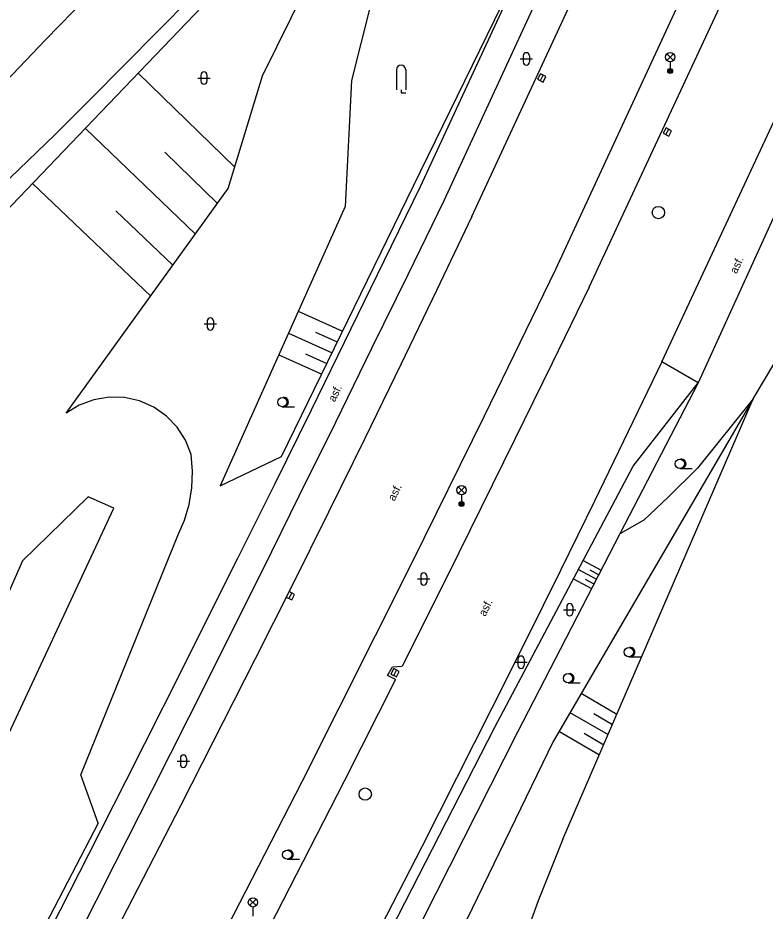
# Model space of a CAD drawing. Extents: x -596024 to -594475, y -1163820 to -1161957.
# Drawn here: x -595661.6 to -595600.9, y -1162932.2 to -1162859.7 of the extents above; entities that cross this region are included whole.
import ezdxf

# ---------------------------------------------------------------- set-up
doc = ezdxf.new("R2010")
doc.units = 0
for name, color, linetype in [('Level 10', 7, 'Continuous'), ('Level 11', 7, 'Continuous'), ('Level 14', 7, 'Continuous'), ('Level 15', 7, 'Continuous'), ('Level 27', 7, 'Continuous'), ('Level 33', 7, 'Continuous'), ('Level 36', 7, 'Continuous'), ('Level 40', 7, 'Continuous')]:
    doc.layers.add(name, color=color, linetype=linetype)

msp = doc.modelspace()

# ---------------------------------------------------------------- linework, layer by layer
at = {"layer": 'Level 10'}
for points in [[(-595666.85, -1162869.3), (-595659.35, -1162861.44), (-595655.97, -1162857.97), (-595636.92, -1162838.39)], [(-595609.25, -1162887.61), (-595595.09, -1162857.2), (-595590.93, -1162847.22)], [(-595642.02, -1162852.43), (-595655.68, -1162866.28)], [(-595624.69, -1162875.81), (-595613.55, -1162851.79)], [(-595617.87, -1162880.07), (-595606.7, -1162855.95)], [(-595615.16, -1162881.55), (-595603.8, -1162857.18)], [(-595655.68, -1162866.28), (-595658.6, -1162869.16)], [(-595658.6, -1162869.16), (-595667.34, -1162877.57)], [(-595624.69, -1162875.81), (-595627.57, -1162881.82), (-595630.47, -1162887.83), (-595633.4, -1162893.82), (-595636.34, -1162899.8), (-595639.31, -1162905.77), (-595642.3, -1162911.73), (-595648.35, -1162923.62), (-595651.4, -1162929.55), (-595654.48, -1162935.46)], [(-595647.58, -1162939.39), (-595641.51, -1162927.59), (-595638.5, -1162921.68), (-595632.53, -1162909.83), (-595629.56, -1162903.89), (-595623.68, -1162892), (-595620.77, -1162886.04), (-595617.87, -1162880.07)], [(-595615.16, -1162881.55), (-595618.17, -1162887.72), (-595621.19, -1162893.88), (-595625.75, -1162903.11), (-595628.82, -1162909.25), (-595630.36, -1162912.32)], [(-595609.25, -1162887.61), (-595611.98, -1162893.26), (-595614.73, -1162898.91), (-595617.49, -1162904.55), (-595620.28, -1162910.17), (-595623.09, -1162915.79), (-595628.77, -1162926.99), (-595631.63, -1162932.57), (-595634.52, -1162938.15), (-595637.43, -1162943.71), (-595640.83, -1162950.2), (-595641.83, -1162952.08)], [(-595630.9, -1162913.4), (-595631.56, -1162913.09), (-595631.14, -1162912.37), (-595630.36, -1162912.32)], [(-595630.9, -1162913.4), (-595635.07, -1162921.66), (-595637.88, -1162927.16), (-595644.94, -1162940.88), (-595648.1, -1162946.98), (-595654.57, -1162959.11), (-595657.88, -1162965.13), (-595661.23, -1162971.12), (-595664.64, -1162977.09), (-595671.6, -1162988.94), (-595675.15, -1162994.82), (-595678.75, -1163000.67)]]:
    msp.add_lwpolyline(points, dxfattribs=at)
at = {"layer": 'Level 11'}
for points in [[(-595628.87, -1162873.35), (-595618.01, -1162849.92)], [(-595615.97, -1162850.7), (-595626.98, -1162874.52)], [(-595592.14, -1162858.24), (-595606.31, -1162889.3)], [(-595658.89, -1162933.6), (-595655.83, -1162927.6), (-595652.78, -1162921.6), (-595649.75, -1162915.59), (-595643.72, -1162903.56), (-595640.72, -1162897.53), (-595637.74, -1162891.49), (-595631.81, -1162879.4), (-595628.87, -1162873.35)], [(-595626.98, -1162874.52), (-595629.91, -1162880.53), (-595632.84, -1162886.53), (-595635.79, -1162892.53), (-595638.75, -1162898.52), (-595641.72, -1162904.51), (-595647.7, -1162916.46), (-595650.71, -1162922.43), (-595653.73, -1162928.39), (-595656.76, -1162934.35)], [(-595606.31, -1162889.3), (-595609.25, -1162887.61)]]:
    msp.add_lwpolyline(points, dxfattribs=at)
at = {"layer": 'Level 14'}
for points in [[(-595641.72, -1162864.38), (-595632.4, -1162845.51)], [(-595629.74, -1162845.95), (-595634.48, -1162864.75)], [(-595628.88, -1162872.15), (-595618.01, -1162849.92)], [(-595640.93, -1162852.78), (-595654.84, -1162867.33)], [(-595644.49, -1162873.53), (-595641.72, -1162864.38)], [(-595634.48, -1162864.75), (-595634.98, -1162874.99)], [(-595654.84, -1162867.33), (-595665.74, -1162878.67)], [(-595601.84, -1162890.6), (-595588.98, -1162869.09)], [(-595640.16, -1162895.29), (-595628.88, -1162872.15)], [(-595657.67, -1162891.78), (-595644.49, -1162873.53)], [(-595634.98, -1162874.99), (-595645.16, -1162897.67)], [(-595606.31, -1162889.3), (-595612.66, -1162901.56)], [(-595611.58, -1162896.08), (-595606.31, -1162889.3)], [(-595648.58, -1162901.72), (-595648.05, -1162900.47), (-595647.68, -1162899.18), (-595647.46, -1162897.84), (-595647.4, -1162896.49), (-595647.5, -1162895.14), (-595647.97, -1162893.97), (-595648.65, -1162892.92), (-595649.52, -1162892.01), (-595650.55, -1162891.29), (-595651.7, -1162890.78), (-595652.93, -1162890.51), (-595654.18, -1162890.47), (-595655.42, -1162890.68), (-595656.6, -1162891.12), (-595657.67, -1162891.78)], [(-595601.84, -1162890.6), (-595618.1, -1162918.43)], [(-595617.29, -1162926.37), (-595601.84, -1162890.6)], [(-595601.84, -1162890.6), (-595606.36, -1162896.25)], [(-595645.16, -1162897.67), (-595640.16, -1162895.29)], [(-595622.83, -1162917.27), (-595611.58, -1162896.08)], [(-595606.36, -1162896.25), (-595608.75, -1162898.59)], [(-595653.8, -1162899.5), (-595655.89, -1162898.57), (-595661.22, -1162903.76), (-595672.02, -1162928.27), (-595680.8, -1162945.81), (-595691.23, -1162965.13), (-595695.5, -1162972.6), (-595709.49, -1162982.92)], [(-595608.75, -1162898.59), (-595610.72, -1162900.46)], [(-595694, -1162973.34), (-595689.15, -1162966.33), (-595677.69, -1162948.07), (-595668.07, -1162930.04), (-595656.91, -1162906.16), (-595653.8, -1162899.5)], [(-595610.72, -1162900.46), (-595612.66, -1162901.56)], [(-595656.47, -1162921.15), (-595648.58, -1162901.72)], [(-595612.66, -1162901.56), (-595621, -1162917.67)], [(-595636.88, -1162944.7), (-595622.83, -1162917.27)], [(-595621, -1162917.67), (-595635.37, -1162946.08)], [(-595618.1, -1162918.43), (-595632.55, -1162948.24)], [(-595655.07, -1162925.07), (-595656.47, -1162921.15)], [(-595655.07, -1162925.07), (-595659.36, -1162933.31)], [(-595617.29, -1162926.37), (-595619.32, -1162931.37), (-595620.7, -1162935.17), (-595621.54, -1162937.73), (-595622.29, -1162940.15), (-595623.72, -1162944.65), (-595624.86, -1162948), (-595626.2, -1162951.77), (-595627.28, -1162954.87), (-595628.34, -1162957.98), (-595629.37, -1162961.09), (-595630.38, -1162964.22), (-595631.21, -1162966.82), (-595631.94, -1162968.89), (-595632.76, -1162970.93), (-595634.11, -1162973.93), (-595635.11, -1162975.89), (-595636.24, -1162977.96), (-595638.63, -1162982.01), (-595639.88, -1162984.01), (-595641.18, -1162985.97)]]:
    msp.add_lwpolyline(points, dxfattribs=at)
at = {"layer": 'Level 15'}
for points in [[(-595651.82, -1162864.17), (-595643.97, -1162871.8)], [(-595656.11, -1162868.65), (-595647.17, -1162877.24)], [(-595649.66, -1162870.57), (-595645.36, -1162874.73)], [(-595660.41, -1162873.12), (-595650.8, -1162882.27)], [(-595653.63, -1162875.33), (-595648.99, -1162879.76)], [(-595638.8, -1162883.5), (-595635.2, -1162885.12)], [(-595639.59, -1162885.27), (-595636.05, -1162886.86)], [(-595637.41, -1162885.19), (-595635.63, -1162885.99)], [(-595640.39, -1162887.04), (-595636.9, -1162888.6)], [(-595638.23, -1162886.94), (-595636.48, -1162887.73)], [(-595615.65, -1162903.75), (-595614.19, -1162904.52)], [(-595616.04, -1162904.48), (-595614.57, -1162905.26)], [(-595615.12, -1162904.5), (-595614.38, -1162904.89)], [(-595616.43, -1162905.22), (-595614.96, -1162906)], [(-595615.5, -1162905.24), (-595614.77, -1162905.63)], [(-595615.81, -1162914.52), (-595612.91, -1162916.23)], [(-595616.72, -1162916.07), (-595613.62, -1162917.87)], [(-595614.77, -1162916.17), (-595613.27, -1162917.05)], [(-595617.62, -1162917.61), (-595614.33, -1162919.52)], [(-595615.57, -1162917.77), (-595613.98, -1162918.7)]]:
    msp.add_lwpolyline(points, dxfattribs=at)
at = {"layer": 'Level 27'}
for p, q in [((-595619.128, -1162864.761), (-595618.892, -1162864.319)), ((-595608.918, -1162869.151), (-595608.682, -1162868.709)), ((-595639.558, -1162906.821), (-595639.322, -1162906.379)), ((-595631.048, -1162913.081), (-595630.812, -1162912.639))]:
    msp.add_line(p, q, dxfattribs=at)
for points in [[(-595618.907, -1162864.878), (-595618.672, -1162864.437), (-595619.113, -1162864.202), (-595619.348, -1162864.643)], [(-595608.697, -1162869.268), (-595608.462, -1162868.827), (-595608.903, -1162868.592), (-595609.138, -1162869.033)], [(-595639.337, -1162906.938), (-595639.102, -1162906.497), (-595639.543, -1162906.262), (-595639.778, -1162906.703)], [(-595630.827, -1162913.198), (-595630.592, -1162912.757), (-595631.033, -1162912.522), (-595631.268, -1162912.963)]]:
    msp.add_lwpolyline(points, close=True, dxfattribs=at)
for centre in [(-595609.54, -1162875.48), (-595633.36, -1162922.71)]:
    msp.add_circle(centre, 0.5, dxfattribs=at)
at = {"layer": 'Level 33'}
for p, q in [((-595608.845, -1162863.12), (-595608.315, -1162862.59)), ((-595608.845, -1162862.59), (-595608.315, -1162863.12)), ((-595608.58, -1162863.23), (-595608.58, -1162863.98)), ((-595625.805, -1162898.29), (-595625.275, -1162897.76)), ((-595625.805, -1162897.76), (-595625.275, -1162898.29)), ((-595625.54, -1162898.4), (-595625.54, -1162899.15)), ((-595642.755, -1162931.77), (-595642.225, -1162931.24)), ((-595642.755, -1162931.24), (-595642.225, -1162931.77)), ((-595642.49, -1162931.88), (-595642.49, -1162932.63))]:
    msp.add_line(p, q, dxfattribs=at)
for centre, radius in [((-595608.58, -1162862.855), 0.375), ((-595608.58, -1162863.98), 0.2), ((-595608.58, -1162863.98), 0.145), ((-595608.58, -1162863.98), 0.0876), ((-595625.54, -1162898.025), 0.375), ((-595625.54, -1162899.15), 0.2), ((-595625.54, -1162899.15), 0.145), ((-595625.54, -1162899.15), 0.0876), ((-595642.49, -1162931.505), 0.375)]:
    msp.add_circle(centre, radius, dxfattribs=at)
at = {"layer": 'Level 36'}
for p, q in [((-595620.766, -1162862.996), (-595619.766, -1162862.996)), ((-595620.516, -1162862.746), (-595620.516, -1162863.246)), ((-595620.016, -1162862.746), (-595620.016, -1162863.246)), ((-595630.825, -1162863.875), (-595630.825, -1162865.5)), ((-595630.075, -1162863.875), (-595630.075, -1162865.5)), ((-595646.976, -1162864.556), (-595645.976, -1162864.556)), ((-595646.726, -1162864.306), (-595646.726, -1162864.806)), ((-595646.226, -1162864.306), (-595646.226, -1162864.806)), ((-595646.196, -1162884.276), (-595646.196, -1162884.776)), ((-595645.696, -1162884.276), (-595645.696, -1162884.776)), ((-595646.446, -1162884.526), (-595645.446, -1162884.526)), ((-595640.1, -1162891.245), (-595639.1, -1162891.245)), ((-595607.79, -1162896.255), (-595606.79, -1162896.255)), ((-595629.106, -1162905.236), (-595628.106, -1162905.236)), ((-595628.856, -1162904.986), (-595628.856, -1162905.486)), ((-595628.356, -1162904.986), (-595628.356, -1162905.486)), ((-595616.986, -1162907.486), (-595616.986, -1162907.986)), ((-595616.486, -1162907.486), (-595616.486, -1162907.986)), ((-595617.236, -1162907.736), (-595616.236, -1162907.736)), ((-595620.956, -1162911.746), (-595620.956, -1162912.246)), ((-595620.456, -1162911.746), (-595620.456, -1162912.246)), ((-595611.94, -1162911.555), (-595610.94, -1162911.555)), ((-595621.206, -1162911.996), (-595620.206, -1162911.996)), ((-595616.88, -1162913.675), (-595615.88, -1162913.675)), ((-595648.386, -1162919.786), (-595648.386, -1162920.286)), ((-595647.886, -1162919.786), (-595647.886, -1162920.286)), ((-595648.636, -1162920.036), (-595647.636, -1162920.036)), ((-595639.71, -1162928.005), (-595638.71, -1162928.005))]:
    msp.add_line(p, q, dxfattribs=at)
msp.add_lwpolyline([(-595630.45, -1162865.5), (-595630.45, -1162865.75), (-595630.075, -1162865.75)], dxfattribs=at)
for centre in [(-595640.1, -1162890.87), (-595607.79, -1162895.88), (-595611.94, -1162911.18), (-595616.88, -1162913.3), (-595639.71, -1162927.63)]:
    msp.add_circle(centre, 0.375, dxfattribs=at)
for centre, radius, start, end in [((-595620.266, -1162862.746), 0.25, 0, 180), ((-595620.266, -1162863.246), 0.25, 180, 0), ((-595630.45, -1162863.875), 0.375, 0, 180), ((-595646.476, -1162864.306), 0.25, 0, 180), ((-595646.476, -1162864.806), 0.25, 180, 0), ((-595645.946, -1162884.276), 0.25, 0, 180), ((-595645.946, -1162884.776), 0.25, 180, 0), ((-595639.975, -1162890.87), 0.375, 260.40593, 99.59407), ((-595607.665, -1162895.88), 0.375, 260.40593, 99.59407), ((-595628.606, -1162904.986), 0.25, 0, 180), ((-595628.606, -1162905.486), 0.25, 180, 0), ((-595616.736, -1162907.486), 0.25, 0, 180), ((-595616.736, -1162907.986), 0.25, 180, 0), ((-595611.815, -1162911.18), 0.375, 260.40593, 99.59407), ((-595620.706, -1162911.746), 0.25, 0, 180), ((-595620.706, -1162912.246), 0.25, 180, 0), ((-595616.755, -1162913.3), 0.375, 260.40593, 99.59407), ((-595648.136, -1162919.786), 0.25, 0, 180), ((-595648.136, -1162920.286), 0.25, 180, 0), ((-595639.585, -1162927.63), 0.375, 260.40593, 99.59407)]:
    msp.add_arc(centre, radius, start, end, dxfattribs=at)

# ---------------------------------------------------------------- texts
at = {"layer": 'Level 40'}
for rotation, p in [(64.83, (-595603.18, -1162880.5)), (64.46, (-595635.83, -1162890.91)), (63.33, (-595630.99, -1162898.96)), (63.33, (-595623.61, -1162908.33))]:
    msp.add_text('asf.', height=0.65, rotation=rotation, dxfattribs=at).set_placement(p)

doc.saveas('drawing.dxf')
